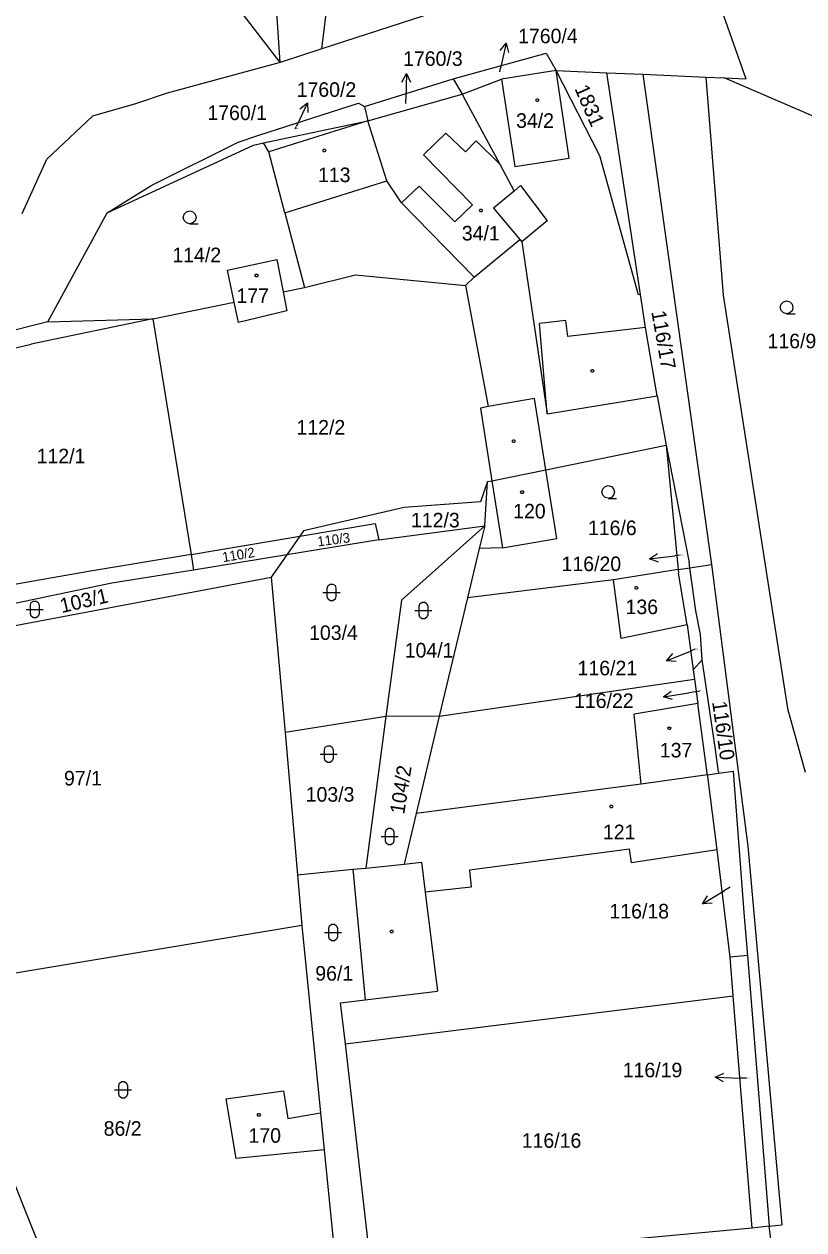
# Model space of a CAD drawing. Extents: x -799786 to -795190, y -1021716 to -1017834.
# Drawn here: x -797858.7 to -797767.7, y -1019054.3 to -1018913.6 of the extents above; entities that cross this region are included whole.
import ezdxf

# ---------------------------------------------------------------- set-up
doc = ezdxf.new("R2010")
doc.units = 0
for name, color, linetype in [('Default', 7, 'Continuous'), ('KN_HRANICE', 7, 'Continuous'), ('KN_KULTURY', 7, 'Continuous'), ('KN_PARCELY', 7, 'Continuous'), ('KN_SLUCKY', 7, 'Continuous')]:
    doc.layers.add(name, color=color, linetype=linetype)

# ---------------------------------------------------------------- blocks, each defined once
blk = doc.blocks.new('304')
at = {"layer": 'Default'}
blk.add_lwpolyline([(0, 0), (-0.38, 0.1), (-0.65, 0.37), (-0.75, 0.74), (-0.65, 1.11), (-0.38, 1.38), (-0.01, 1.48), (0.36, 1.38), (0.63, 1.11), (0.73, 0.73), (0.63, 0.35), (0.36, 0.08), (-0.02, -0.02), (0.98, -0.02)], dxfattribs=at)
blk = doc.blocks.new('316')
at = {"layer": 'Default'}
for points in [[(-0.5, 1.5), (-0.4, 1.79), (-0.15, 1.97), (0.16, 1.97), (0.41, 1.79), (0.51, 1.5), (0.51, 0.5), (0.41, 0.21), (0.16, 0.03), (-0.15, 0.03), (-0.4, 0.21), (-0.5, 0.5), (-0.5, 1.5)], [(-1, 1), (0.27, 1), (1, 1)]]:
    blk.add_lwpolyline(points, dxfattribs=at)
blk = doc.blocks.new('10292')
at = {"layer": 'Default'}
blk.add_line((0, 3), (0, 0), dxfattribs=at)
blk.add_lwpolyline([(-0.5, 2), (0, 3), (0.5, 2)], dxfattribs=at)
blk = doc.blocks.new('402')
at = {"layer": 'Default'}
blk.add_lwpolyline([(0.09, 0.15), (0.18, 0), (0.09, -0.15), (-0.09, -0.15), (-0.18, 0), (-0.09, 0.15), (0.09, 0.15)], dxfattribs=at)

msp = doc.modelspace()

# ---------------------------------------------------------------- linework, layer by layer
at = {"layer": 'KN_HRANICE'}
for p, q in [((-797828.8, -1018918.06), (-797830.76, -1018887.66)), ((-797780.6, -1018902.35), (-797774.45, -1018919.96)), ((-797828.8, -1018918.06), (-797840.06, -1018903.4)), ((-797823.92, -1018916.47), (-797822.94, -1018908.49)), ((-797802.04, -1018909.37), (-797823.92, -1018916.47)), ((-797823.92, -1018916.47), (-797828.8, -1018918.06)), ((-797828.8, -1018918.06), (-797841.98, -1018921.65)), ((-797808.58, -1018919.95), (-797797.72, -1018916.99)), ((-797797.72, -1018916.99), (-797796.59, -1018919)), ((-797796.59, -1018919), (-797802.96, -1018919.99)), ((-797796.59, -1018919), (-797790.65, -1018919.26)), ((-797790.65, -1018919.26), (-797786.47, -1018919.44)), ((-797786.74, -1018945.13), (-797790.65, -1018919.26)), ((-797786.47, -1018919.44), (-797778.44, -1018976.64)), ((-797786.47, -1018919.44), (-797779.12, -1018919.76)), ((-797818.96, -1018923.18), (-797808.58, -1018919.95)), ((-797808.58, -1018919.95), (-797807.55, -1018921.77)), ((-797807.55, -1018921.77), (-797802.96, -1018919.99)), ((-797779.12, -1018919.76), (-797777.07, -1018945.2)), ((-797779.12, -1018919.76), (-797776.98, -1018919.85)), ((-797776.98, -1018919.85), (-797774.45, -1018919.96)), ((-797762.92, -1018925.93), (-797776.98, -1018919.85)), ((-797841.98, -1018921.65), (-797845.66, -1018922.89)), ((-797818.57, -1018924.86), (-797807.55, -1018921.77)), ((-797845.66, -1018922.89), (-797850.7, -1018924.31)), ((-797831.26, -1018926.55), (-797819.65, -1018922.79)), ((-797819.65, -1018922.79), (-797818.96, -1018923.18)), ((-797818.96, -1018923.18), (-797818.57, -1018924.86)), ((-797856.04, -1018929.36), (-797850.7, -1018924.31)), ((-797830.73, -1018927.45), (-797818.57, -1018924.86)), ((-797816.35, -1018931.88), (-797818.57, -1018924.86)), ((-797833.69, -1018927.34), (-797831.26, -1018926.55)), ((-797848.98, -1018935.61), (-797831.9, -1018927.7)), ((-797843.78, -1018932.39), (-797833.69, -1018927.34)), ((-797831.9, -1018927.7), (-797830.73, -1018927.45)), ((-797830.11, -1018928.49), (-797830.73, -1018927.45)), ((-797858.91, -1018935.69), (-797856.04, -1018929.36)), ((-797828.23, -1018935.61), (-797830.11, -1018928.49)), ((-797803.15, -1018929.93), (-797801.46, -1018933.06)), ((-797814.61, -1018934.45), (-797816.35, -1018931.88)), ((-797848.98, -1018935.61), (-797843.78, -1018932.39)), ((-797814.61, -1018934.45), (-797806.14, -1018943.1)), ((-797853.79, -1018944.47), (-797848.98, -1018935.61)), ((-797828.23, -1018935.61), (-797825.93, -1018944.32)), ((-797800.8, -1018938.71), (-797800.56, -1018938.99)), ((-797800.56, -1018938.99), (-797797.61, -1018959.07)), ((-797834.15, -1018946.02), (-797834.93, -1018942.31)), ((-797825.93, -1018944.32), (-797820.01, -1018942.84)), ((-797820.01, -1018942.84), (-797807.15, -1018944.1)), ((-797807.15, -1018944.1), (-797806.14, -1018943.1)), ((-797855.89, -1018948.34), (-797853.79, -1018944.47)), ((-797828.43, -1018944.84), (-797825.93, -1018944.32)), ((-797807.15, -1018944.1), (-797804.49, -1018958.21)), ((-797843.64, -1018947.99), (-797834.15, -1018946.02)), ((-797786.15, -1018949), (-797786.74, -1018945.13)), ((-797777.07, -1018945.2), (-797769.56, -1018993.42)), ((-797855.89, -1018948.34), (-797887.74, -1018956.13)), ((-797843.64, -1018947.99), (-797857.87, -1018950.94)), ((-797855.89, -1018948.34), (-797843.64, -1018947.99)), ((-797843.64, -1018947.99), (-797839.19, -1018975.46)), ((-797784.77, -1018956.97), (-797786.15, -1018949)), ((-797869.28, -1018953.62), (-797857.87, -1018950.94)), ((-797797.61, -1018959.07), (-797784.77, -1018956.97)), ((-797784.77, -1018956.97), (-797783.74, -1018962.73)), ((-797804.49, -1018958.21), (-797805.41, -1018958.41)), ((-797805.41, -1018958.41), (-797804.08, -1018966.87)), ((-797797.77, -1018965.58), (-797783.74, -1018962.73)), ((-797783.74, -1018962.73), (-797781.05, -1018976.41)), ((-797783.74, -1018962.73), (-797782.32, -1018977.22)), ((-797804.08, -1018966.87), (-797797.77, -1018965.58)), ((-797796.48, -1018973.6), (-797797.77, -1018965.58)), ((-797804.58, -1018966.97), (-797805.42, -1018969.31)), ((-797804.9, -1018972.11), (-797804.58, -1018966.97)), ((-797804.58, -1018966.97), (-797804.08, -1018966.87)), ((-797814.3, -1018969.98), (-797826.06, -1018972.7)), ((-797805.42, -1018969.31), (-797814.3, -1018969.98)), ((-797826.5, -1018973.34), (-797817.69, -1018971.86)), ((-797826.06, -1018972.7), (-797826.5, -1018973.34)), ((-797817.69, -1018971.86), (-797817.27, -1018973.75)), ((-797817.27, -1018973.75), (-797804.9, -1018972.11)), ((-797804.9, -1018972.11), (-797814.64, -1018980.78)), ((-797804.9, -1018972.11), (-797805.54, -1018974.76)), ((-797839.19, -1018975.46), (-797826.5, -1018973.34)), ((-797826.5, -1018973.34), (-797828.01, -1018975.5)), ((-797817.27, -1018973.75), (-797828.01, -1018975.5)), ((-797802.85, -1018974.69), (-797796.48, -1018973.6)), ((-797839.19, -1018975.46), (-797851.15, -1018977.47)), ((-797839.19, -1018975.46), (-797838.9, -1018977.28)), ((-797828.01, -1018975.5), (-797838.9, -1018977.28)), ((-797828.01, -1018975.5), (-797829.82, -1018978.1)), ((-797805.54, -1018974.76), (-797806.93, -1018980.51)), ((-797802.85, -1018974.69), (-797805.54, -1018974.76)), ((-797782.32, -1018977.22), (-797789.86, -1018978.41)), ((-797782.32, -1018977.22), (-797780.96, -1018977.01)), ((-797782.32, -1018977.22), (-797782.28, -1018977.63)), ((-797780.96, -1018977.01), (-797781.05, -1018976.41)), ((-797780.96, -1018977.01), (-797778.44, -1018976.64)), ((-797780.25, -1018982.05), (-797780.96, -1018977.01)), ((-797778.44, -1018976.64), (-797774.19, -1019009.52)), ((-797876.31, -1018986.88), (-797829.82, -1018978.1)), ((-797851.15, -1018977.47), (-797868.08, -1018980.41)), ((-797838.9, -1018977.28), (-797848.43, -1018978.83)), ((-797829.82, -1018978.1), (-797828.22, -1018996.24)), ((-797789.86, -1018978.41), (-797806.93, -1018980.51)), ((-797781.28, -1018983.68), (-797782.28, -1018977.63)), ((-797848.43, -1018978.83), (-797876.06, -1018984.55)), ((-797814.64, -1018980.78), (-797816.44, -1018994.37)), ((-797806.93, -1018980.51), (-797810.22, -1018994.34)), ((-797779.74, -1018984.79), (-797780.25, -1018982.05)), ((-797781.28, -1018983.68), (-797780.57, -1018988.91)), ((-797779.51, -1018987.75), (-797779.74, -1018984.79)), ((-797779.51, -1018987.75), (-797780.57, -1018988.91)), ((-797777.99, -1018998.21), (-797779.51, -1018987.75)), ((-797780.57, -1018988.91), (-797780.42, -1018990)), ((-797810.22, -1018994.34), (-797780.42, -1018990)), ((-797780.42, -1018990), (-797780.03, -1018992.84)), ((-797778.93, -1019000.97), (-797780.03, -1018992.84)), ((-797769.56, -1018993.42), (-797767.5, -1019000.85)), ((-797816.44, -1018994.37), (-797828.22, -1018996.24)), ((-797816.44, -1018994.37), (-797818.77, -1019012.05)), ((-797810.22, -1018994.34), (-797816.44, -1018994.37)), ((-797810.22, -1018994.34), (-797812.92, -1019005.71)), ((-797828.22, -1018996.24), (-797826.76, -1019012.84)), ((-797777.62, -1019000.83), (-797777.99, -1018998.21)), ((-797778.9, -1019001.18), (-797778.93, -1019000.97)), ((-797778.9, -1019001.18), (-797777.6, -1019001)), ((-797777.62, -1019000.83), (-797777.6, -1019001)), ((-797777.6, -1019001), (-797775.91, -1019000.77)), ((-797775.91, -1019000.77), (-797774.61, -1019017.76)), ((-797786.65, -1019002.28), (-797812.92, -1019005.71)), ((-797778.9, -1019001.18), (-797786.65, -1019002.28)), ((-797778.88, -1019001.39), (-797778.9, -1019001.18)), ((-797777.77, -1019009.92), (-797778.88, -1019001.39)), ((-797812.92, -1019005.71), (-797814.33, -1019011.61)), ((-797774.19, -1019009.52), (-797770.23, -1019053.7)), ((-797776.28, -1019022.46), (-797777.77, -1019009.92)), ((-797826.76, -1019012.84), (-797820.29, -1019012.2)), ((-797820.29, -1019012.2), (-797818.77, -1019012.05)), ((-797820.29, -1019012.2), (-797818.87, -1019027.43)), ((-797818.77, -1019012.05), (-797814.33, -1019011.61)), ((-797826.76, -1019012.84), (-797826.24, -1019018.74)), ((-797774.61, -1019017.76), (-797774.25, -1019022.25)), ((-797826.24, -1019018.74), (-797867.23, -1019025.59)), ((-797826.24, -1019018.74), (-797824.07, -1019040.62)), ((-797774.25, -1019022.25), (-797776.28, -1019022.46)), ((-797774.25, -1019022.25), (-797771.72, -1019053.85)), ((-797775.91, -1019026.96), (-797776.28, -1019022.46)), ((-797852.67, -1019066.58), (-797869.05, -1019025.87)), ((-797821.73, -1019027.77), (-797818.87, -1019027.43)), ((-797821.18, -1019032.56), (-797821.73, -1019027.77)), ((-797821.18, -1019032.56), (-797775.91, -1019026.96)), ((-797773.7, -1019054.09), (-797775.91, -1019026.96)), ((-797818.22, -1019058.17), (-797821.18, -1019032.56)), ((-797835.1, -1019038.98), (-797828.41, -1019038.06)), ((-797833.94, -1019045.93), (-797835.1, -1019038.98)), ((-797828.41, -1019038.06), (-797827.89, -1019041.26)), ((-797827.89, -1019041.26), (-797824.07, -1019040.62)), ((-797824.07, -1019040.62), (-797823.64, -1019044.95)), ((-797823.64, -1019044.95), (-797833.94, -1019045.93)), ((-797823.64, -1019044.95), (-797822.2, -1019059.5)), ((-797773.7, -1019054.09), (-797816.3, -1019057.99)), ((-797771.72, -1019053.85), (-797773.7, -1019054.09)), ((-797771.72, -1019053.85), (-797770.23, -1019053.7)), ((-797767.35, -1019085.59), (-797771.72, -1019053.85))]:
    msp.add_line(p, q, dxfattribs=at)
for points in [[(-797786.74, -1018945.13), (-797786.96, -1018945.16), (-797791.48, -1018928.97), (-797796.59, -1018919)], [(-797807.55, -1018921.77), (-797807.1, -1018922.58), (-797803.15, -1018929.93)], [(-797801.46, -1018933.06), (-797803.88, -1018935.06), (-797800.8, -1018938.71)], [(-797834.93, -1018942.31), (-797829.18, -1018941.06), (-797828.43, -1018944.84)], [(-797828.43, -1018944.84), (-797827.99, -1018947.02), (-797833.64, -1018948.41), (-797834.15, -1018946.02)]]:
    msp.add_lwpolyline(points, dxfattribs=at)
at = {"layer": 'KN_PARCELY'}
for p, q in [((-797803.16, -1018919.15), (-797803.07, -1018918.74)), ((-797814.13, -1018922.84), (-797814.12, -1018922.36)), ((-797827.04, -1018925.82), (-797826.88, -1018925.48)), ((-797782.16, -1018975.55), (-797782.71, -1018975.62)), ((-797780.37, -1018986.52), (-797780.9, -1018986.74)), ((-797779.82, -1018991.41), (-797781.09, -1018991.61)), ((-797776.27, -1019014.28), (-797776.92, -1019014.68)), ((-797774.37, -1019036.58), (-797775.01, -1019036.56))]:
    msp.add_line(p, q, dxfattribs=at)
at = {"layer": 'KN_SLUCKY'}
for p, q in [((-797795.04, -1018929.22), (-797796.59, -1018919)), ((-797818.57, -1018924.86), (-797830.11, -1018928.49)), ((-797812.06, -1018928.83), (-797809.46, -1018926.29)), ((-797809.46, -1018926.29), (-797807.17, -1018928.48)), ((-797807.17, -1018928.48), (-797805.92, -1018927.19)), ((-797805.92, -1018927.19), (-797803.15, -1018929.93)), ((-797806.34, -1018934.66), (-797812.06, -1018928.83)), ((-797828.23, -1018935.61), (-797816.35, -1018931.88)), ((-797814.61, -1018934.45), (-797812.55, -1018932.51)), ((-797812.55, -1018932.51), (-797808.39, -1018936.64)), ((-797808.39, -1018936.64), (-797806.34, -1018934.66)), ((-797806.14, -1018943.1), (-797800.8, -1018938.71)), ((-797795.43, -1018948.15), (-797798.51, -1018948.52)), ((-797797.61, -1018959.07), (-797798.51, -1018948.52)), ((-797795.22, -1018950.05), (-797795.43, -1018948.15)), ((-797786.15, -1018949), (-797795.22, -1018950.05)), ((-797799.1, -1018957.28), (-797804.49, -1018958.21)), ((-797797.77, -1018965.58), (-797799.1, -1018957.28)), ((-797804.08, -1018966.87), (-797802.85, -1018974.69)), ((-797788.99, -1018985.26), (-797789.86, -1018978.41)), ((-797781.28, -1018983.68), (-797788.99, -1018985.26)), ((-797780.03, -1018992.84), (-797787.47, -1018994.12)), ((-797786.65, -1019002.28), (-797787.47, -1018994.12)), ((-797788.02, -1019009.87), (-797806.67, -1019012.3)), ((-797787.76, -1019011.43), (-797788.02, -1019009.87)), ((-797777.77, -1019009.92), (-797787.76, -1019011.43)), ((-797814.33, -1019011.61), (-797812.29, -1019011.36)), ((-797812.29, -1019011.36), (-797811.85, -1019014.87)), ((-797806.67, -1019012.3), (-797806.48, -1019014.28)), ((-797806.48, -1019014.28), (-797811.85, -1019014.87)), ((-797811.85, -1019014.87), (-797810.42, -1019026.42)), ((-797818.87, -1019027.43), (-797810.42, -1019026.42))]:
    msp.add_line(p, q, dxfattribs=at)
for points in [[(-797802.96, -1018919.99), (-797801.41, -1018930.21), (-797795.04, -1018929.22)], [(-797801.46, -1018933.06), (-797800.74, -1018932.42), (-797797.63, -1018936.54), (-797800.56, -1018938.99)]]:
    msp.add_lwpolyline(points, dxfattribs=at)

# ---------------------------------------------------------------- block references
at = {"layer": 'KN_KULTURY'}
for name, p in [('402', (-797798.78, -1018922.46)), ('402', (-797823.63, -1018928.32)), ('304', (-797839.34, -1018936.87)), ('402', (-797805.33, -1018935.32)), ('402', (-797831.55, -1018942.93)), ('304', (-797769.66, -1018947.37)), ('402', (-797792.34, -1018954.05)), ('402', (-797801.52, -1018962.26)), ('402', (-797800.54, -1018968.19)), ('304', (-797790.49, -1018968.91)), ('316', (-797822.79, -1018980.89)), ('402', (-797787.21, -1018979.36)), ('316', (-797857.44, -1018982.88)), ('316', (-797812.07, -1018983)), ('402', (-797783.37, -1018995.75)), ('316', (-797823.12, -1018999.76)), ('402', (-797790.12, -1019004.87)), ('316', (-797816.01, -1019009.38)), ('316', (-797822.62, -1019020.57)), ('402', (-797815.77, -1019019.46)), ('316', (-797847.13, -1019038.93)), ('402', (-797831.28, -1019040.84))]:
    msp.add_blockref(name, p, dxfattribs=at)
at = {"layer": 'KN_PARCELY'}
for p, rotation in [((-797803.07, -1018918.74), -12.844872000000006), ((-797814.12, -1018922.36), -1.1565330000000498), ((-797826.88, -1018925.48), -25.44994300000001), ((-797782.71, -1018975.62), 96.944459), ((-797780.9, -1018986.74), 112.18513600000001), ((-797781.09, -1018991.61), 98.72062800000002), ((-797776.92, -1019014.68), 121.40975700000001), ((-797775.01, -1019036.56), 88.292796)]:
    msp.add_blockref('10292', p, dxfattribs=dict(at, rotation=rotation))

# ---------------------------------------------------------------- texts
for s, height, p in [('1760/4', 1.7, (-797801.01, -1018915.82)), ('1760/3', 1.7, (-797814.44, -1018918.46)), ('1760/4', 0.1, (-797803.14, -1018919.15)), ('1760/2', 1.7, (-797826.86, -1018922.07)), ('1760/1', 1.7, (-797837.28, -1018924.78)), ('1760/3', 0.1, (-797814.11, -1018922.84)), ('34/2', 1.7, (-797801.25, -1018925.69)), ('1760/2', 0.1, (-797827.02, -1018925.82)), ('113', 1.7, (-797824.37, -1018932.02)), ('34/1', 1.7, (-797807.58, -1018938.83)), ('114/2', 1.7, (-797841.37, -1018941.37)), ('177', 1.7, (-797833.9, -1018946.13)), ('116/9', 1.7, (-797771.9, -1018951.41)), ('112/2', 1.7, (-797826.88, -1018961.48)), ('112/1', 1.7, (-797857.21, -1018964.83)), ('120', 1.7, (-797801.59, -1018971.26)), ('112/3', 1.7, (-797813.52, -1018972.31)), ('116/6', 1.7, (-797792.86, -1018973.21)), ('116/20', 1.7, (-797795.94, -1018977.41)), ('116/20', 0.1, (-797782.14, -1018975.55)), ('136', 1.7, (-797788.47, -1018982.43)), ('103/4', 1.7, (-797825.41, -1018985.44)), ('104/1', 1.7, (-797814.25, -1018987.49)), ('116/21', 0.1, (-797780.35, -1018986.52)), ('116/21', 1.7, (-797794.07, -1018989.57)), ('116/22', 0.1, (-797779.8, -1018991.41)), ('116/22', 1.7, (-797794.48, -1018993.38)), ('137', 1.7, (-797784.47, -1018999.15)), ('97/1', 1.7, (-797854.02, -1019002.42)), ('103/3', 1.7, (-797825.81, -1019004.31)), ('121', 1.7, (-797791.11, -1019008.69)), ('116/18', 0.1, (-797776.25, -1019014.28)), ('116/18', 1.7, (-797790.35, -1019017.94)), ('96/1', 1.7, (-797824.69, -1019025.19)), ('116/19', 1.7, (-797788.8, -1019036.47)), ('116/19', 0.1, (-797774.35, -1019036.58)), ('86/2', 1.7, (-797849.39, -1019043.29)), ('170', 1.7, (-797832.48, -1019044.11)), ('116/16', 1.7, (-797800.59, -1019044.7))]:
    msp.add_text(s, height=height, dxfattribs=at).set_placement(p)
for s, height, rotation, p in [('1831', 1.7, 293.698, (-797794.46, -1018921.1)), ('116/17', 1.7, 280.119, (-797785.47, -1018947.15)), ('110/3', 1.14, 7.506, (-797824.36, -1018974.54)), ('110/2', 1.14, 9.339, (-797835.44, -1018976.37)), ('103/1', 1.7, 12.892, (-797854.28, -1018982.31)), ('116/10', 1.7, 278.056, (-797778.37, -1018992.68)), ('104/2', 1.7, 81.074, (-797814.31, -1019005.84))]:
    msp.add_text(s, height=height, rotation=rotation, dxfattribs=at).set_placement(p)

doc.saveas('drawing.dxf')
